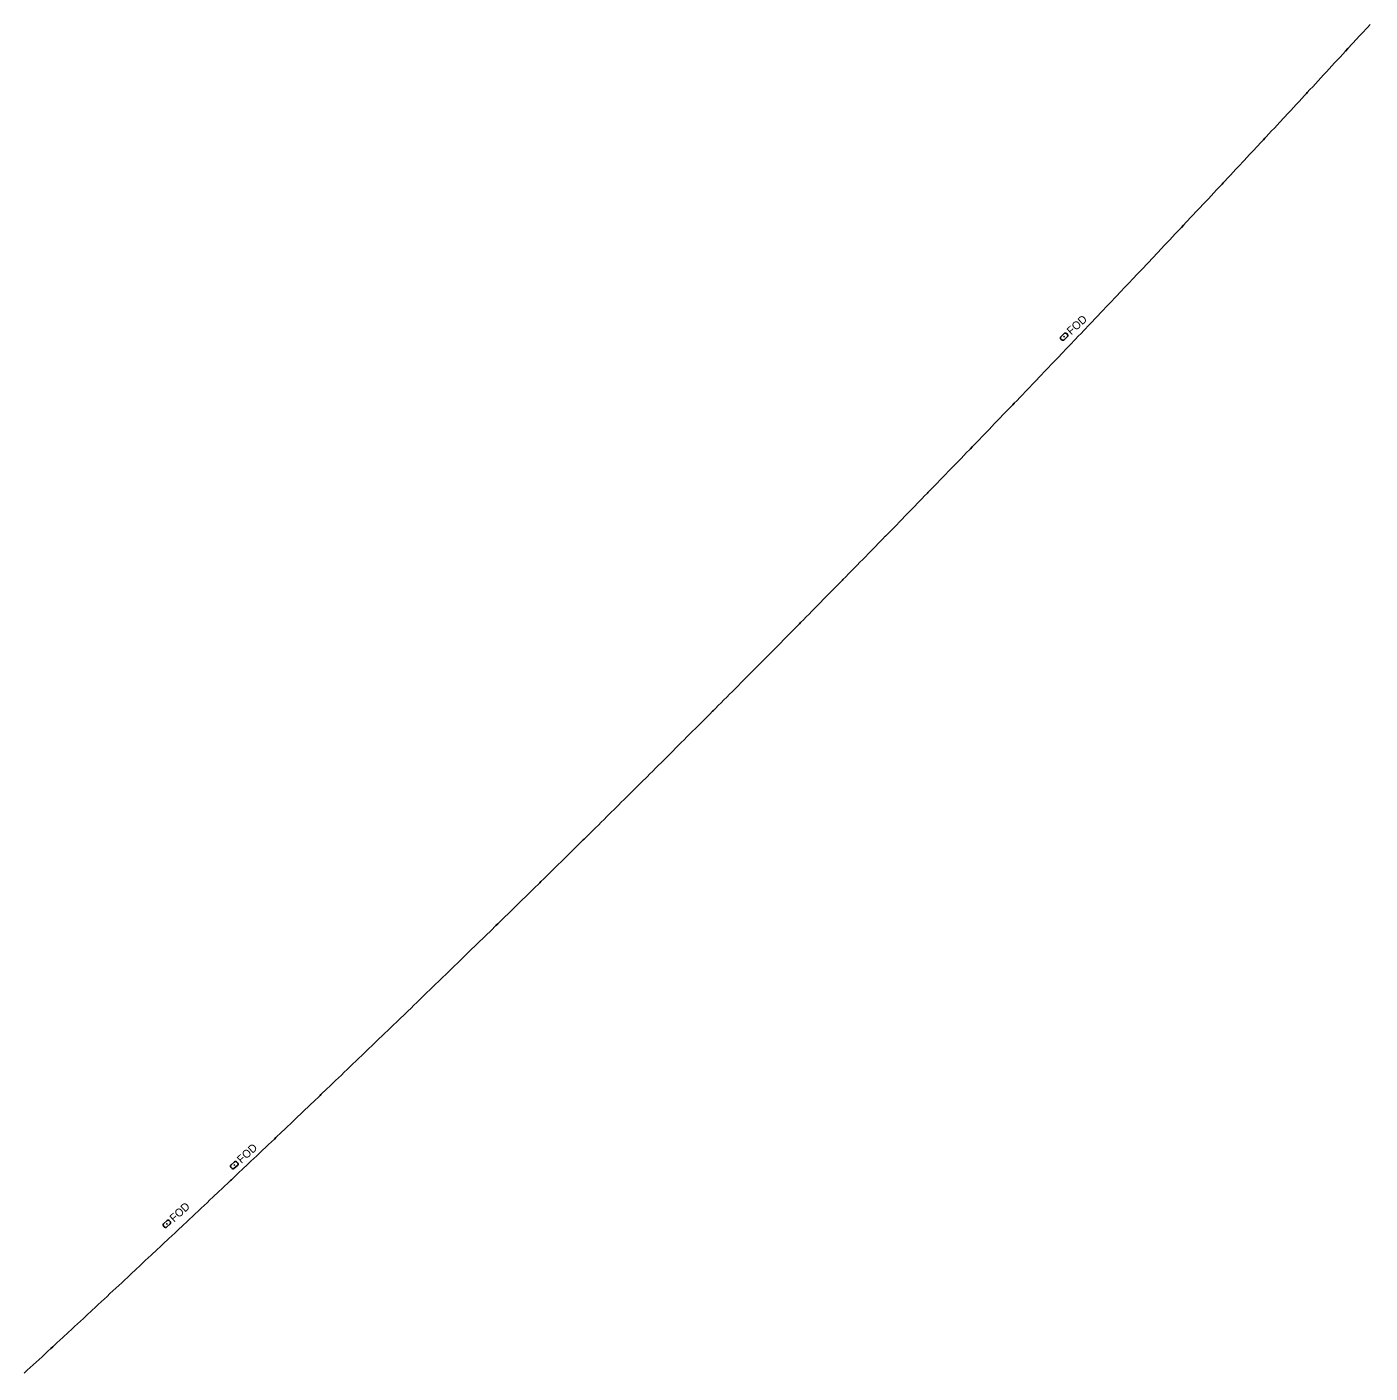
# Model space of a CAD drawing. Extents: x 1738869 to 1765295, y 463516 to 481552.
# Drawn here: x 1757969.7 to 1758301.3, y 478999.7 to 479332 of the extents above; entities that cross this region are included whole.
import ezdxf

# ---------------------------------------------------------------- set-up
doc = ezdxf.new("R2010")
doc.units = 0
doc.layers.add('D_ITS_Fiber', color=7, linetype='Continuous')
doc.layers.add('ITS Sign FO Delineator', color=7, linetype='Continuous')

msp = doc.modelspace()

# ---------------------------------------------------------------- linework, layer by layer
at = {"layer": 'D_ITS_Fiber'}
for points in [[(1758094.49, 479118.95), (1758095.19, 479119.64), (1758095.91, 479120.34), (1758096.3, 479120.72), (1758096.61, 479121.03), (1758097.32, 479121.73), (1758099.46, 479123.82), (1758100.16, 479124.52), (1758100.87, 479125.22), (1758101.59, 479125.92), (1758103.71, 479128.01), (1758104.42, 479128.71), (1758105.13, 479129.4), (1758106.54, 479130.8), (1758107.06, 479131.31), (1758107.25, 479131.5), (1758110.08, 479134.29), (1758110.79, 479134.99), (1758111.5, 479135.69), (1758112.2, 479136.39), (1758112.91, 479137.09), (1758115.74, 479139.89), (1758116.45, 479140.59), (1758117.15, 479141.29), (1758117.78, 479141.91), (1758117.85, 479141.98), (1758118.57, 479142.69), (1758119.27, 479143.39), (1758119.98, 479144.09), (1758120.68, 479144.79), (1758121.39, 479145.5), (1758122.8, 479146.9), (1758123.51, 479147.6), (1758124.21, 479148.3), (1758124.92, 479149), (1758127.03, 479151.11), (1758127.74, 479151.81), (1758128.44, 479152.51), (1758128.49, 479152.56), (1758129.14, 479153.21), (1758129.85, 479153.92), (1758131.26, 479155.33), (1758131.96, 479156.03), (1758132.66, 479156.73), (1758134.07, 479158.14), (1758134.78, 479158.84), (1758135.48, 479159.54), (1758136.18, 479160.25), (1758138.29, 479162.36), (1758139, 479163.07), (1758139.18, 479163.25), (1758139.69, 479163.76), (1758140.4, 479164.47), (1758141.1, 479165.18), (1758141.8, 479165.88), (1758142.51, 479166.59), (1758143.2, 479167.29), (1758143.91, 479167.99), (1758144.61, 479168.7), (1758146.71, 479170.81), (1758148.82, 479172.94), (1758149.52, 479173.64), (1758149.82, 479173.94), (1758150.22, 479174.34), (1758150.92, 479175.05), (1758151.62, 479175.76), (1758152.32, 479176.46), (1758153.02, 479177.17), (1758155.82, 479180), (1758156.52, 479180.71), (1758157.22, 479181.41), (1758157.92, 479182.12), (1758158.62, 479182.83), (1758160.02, 479184.24), (1758160.44, 479184.67), (1758160.71, 479184.95), (1758161.41, 479185.66), (1758162.11, 479186.37), (1758162.81, 479187.07), (1758163.51, 479187.78), (1758164.21, 479188.49), (1758167.69, 479192.03), (1758168.39, 479192.74), (1758170.49, 479194.88), (1758171.03, 479195.43), (1758171.18, 479195.58), (1758171.88, 479196.29), (1758172.57, 479197), (1758173.27, 479197.71), (1758173.97, 479198.42), (1758174.67, 479199.14), (1758175.36, 479199.84), (1758176.06, 479200.56), (1758178.14, 479202.69), (1758180.93, 479205.53), (1758181.64, 479206.26), (1758181.66, 479206.29), (1758183.7, 479208.38), (1758185.79, 479210.52), (1758186.48, 479211.23), (1758187.87, 479212.66), (1758188.56, 479213.37), (1758189.95, 479214.79), (1758190.65, 479215.51), (1758191.34, 479216.22), (1758192.04, 479216.95), (1758192.14, 479217.05), (1758192.73, 479217.65), (1758193.42, 479218.36), (1758194.11, 479219.07), (1758195.5, 479220.5), (1758196.19, 479221.22), (1758197.57, 479222.64), (1758200.34, 479225.5), (1758201.03, 479226.22), (1758201.72, 479226.94), (1758202.41, 479227.65), (1758202.63, 479227.87), (1758203.11, 479228.37), (1758207.25, 479232.66), (1758207.94, 479233.38), (1758208.63, 479234.09), (1758212.08, 479237.67), (1758212.77, 479238.39), (1758213.11, 479238.75), (1758213.46, 479239.11), (1758214.15, 479239.83), (1758214.84, 479240.55), (1758216.9, 479242.7), (1758218.28, 479244.14), (1758218.97, 479244.85), (1758219.66, 479245.57), (1758223.1, 479249.16), (1758223.56, 479249.65), (1758223.78, 479249.88), (1758224.47, 479250.6), (1758225.16, 479251.32), (1758226.53, 479252.76), (1758227.22, 479253.48), (1758228.59, 479254.92), (1758229.28, 479255.64), (1758229.96, 479256.36), (1758230.65, 479257.08), (1758232.02, 479258.52), (1758232.71, 479259.24), (1758233.39, 479259.96), (1758233.97, 479260.56), (1758234.07, 479260.67), (1758234.77, 479261.4), (1758236.82, 479263.57), (1758238.87, 479265.73), (1758239.56, 479266.45), (1758240.93, 479267.9), (1758241.61, 479268.62), (1758242.98, 479270.06), (1758243.67, 479270.79), (1758244.23, 479271.38), (1758244.25, 479271.4), (1758245.03, 479272.23), (1758247.76, 479275.12), (1758249.81, 479277.3), (1758250.49, 479278.02), (1758251.17, 479278.74), (1758251.86, 479279.47), (1758253.22, 479280.91), (1758254.59, 479282.37), (1758254.73, 479282.51), (1758255.27, 479283.09), (1758255.95, 479283.81), (1758258.67, 479286.71), (1758259.36, 479287.44), (1758260.04, 479288.16), (1758260.71, 479288.88), (1758261.4, 479289.61), (1758262.08, 479290.34), (1758262.76, 479291.07), (1758263.44, 479291.79), (1758264.12, 479292.51), (1758264.8, 479293.24), (1758265.05, 479293.51), (1758265.47, 479293.97), (1758266.16, 479294.7), (1758266.84, 479295.42), (1758267.52, 479296.15), (1758268.19, 479296.87), (1758268.87, 479297.6), (1758270.23, 479299.06), (1758270.91, 479299.78), (1758271.59, 479300.51), (1758272.27, 479301.24), (1758273.62, 479302.69), (1758274.3, 479303.42), (1758274.98, 479304.15), (1758275.36, 479304.55), (1758275.66, 479304.88), (1758276.33, 479305.6), (1758277.01, 479306.33), (1758277.69, 479307.06), (1758278.37, 479307.79), (1758279.05, 479308.52), (1758281.07, 479310.71), (1758281.75, 479311.43), (1758282.43, 479312.16), (1758283.1, 479312.89), (1758283.78, 479313.62), (1758284.46, 479314.35), (1758285.13, 479315.08), (1758285.62, 479315.61), (1758285.81, 479315.81), (1758286.48, 479316.54), (1758287.16, 479317.27), (1758287.83, 479318), (1758288.51, 479318.73), (1758289.18, 479319.46), (1758289.86, 479320.2), (1758290.54, 479320.92), (1758291.21, 479321.65), (1758291.89, 479322.39), (1758292.56, 479323.12), (1758293.23, 479323.85), (1758293.91, 479324.58), (1758294.58, 479325.31), (1758295.26, 479326.04), (1758295.85, 479326.69), (1758295.92, 479326.76), (1758297.95, 479328.97), (1758298.62, 479329.7), (1758299.3, 479330.44), (1758300.65, 479331.9), (1758301.32, 479332.64)], [(1757969.06, 478999.68), (1757969.79, 479000.36), (1757973.44, 479003.73), (1757974.17, 479004.41), (1757974.9, 479005.08), (1757975.64, 479005.76), (1757976.08, 479006.17), (1757976.36, 479006.43), (1757977.1, 479007.11), (1757977.82, 479007.78), (1757978.55, 479008.46), (1757980.01, 479009.81), (1757980.74, 479010.48), (1757981.47, 479011.17), (1757982.2, 479011.84), (1757983.66, 479013.19), (1757984.39, 479013.87), (1757985.85, 479015.23), (1757986.57, 479015.9), (1757987.14, 479016.43), (1757987.3, 479016.58), (1757988.03, 479017.26), (1757988.76, 479017.94), (1757989.48, 479018.61), (1757990.21, 479019.29), (1757991.67, 479020.65), (1757992.39, 479021.32), (1757993.12, 479022), (1757993.85, 479022.68), (1757994.58, 479023.36), (1757995.31, 479024.04), (1757996.76, 479025.4), (1757997.48, 479026.08), (1757998.25, 479026.8), (1757998.28, 479026.82), (1757998.94, 479027.44), (1757999.67, 479028.12), (1758000.39, 479028.8), (1758001.84, 479030.15), (1758002.57, 479030.84), (1758003.3, 479031.52), (1758004.75, 479032.88), (1758005.47, 479033.56), (1758006.2, 479034.24), (1758006.92, 479034.92), (1758008.37, 479036.28), (1758009.1, 479036.96), (1758009.2, 479037.06), (1758009.82, 479037.65), (1758010.55, 479038.33), (1758011.27, 479039.01), (1758012, 479039.69), (1758012.72, 479040.37), (1758013.44, 479041.05), (1758014.17, 479041.74), (1758014.89, 479042.42), (1758015.62, 479043.1), (1758017.06, 479044.47), (1758017.79, 479045.15), (1758018.51, 479045.83), (1758019.23, 479046.52), (1758019.95, 479047.2), (1758020.18, 479047.41), (1758020.68, 479047.88), (1758021.4, 479048.57), (1758022.12, 479049.25), (1758022.84, 479049.93), (1758024.29, 479051.3), (1758025.01, 479051.98), (1758025.73, 479052.67), (1758026.46, 479053.35), (1758027.18, 479054.04), (1758029.34, 479056.09), (1758030.79, 479057.47), (1758031.14, 479057.8), (1758031.5, 479058.15), (1758032.23, 479058.83), (1758033.67, 479060.2), (1758035.11, 479061.58), (1758035.83, 479062.26), (1758037.99, 479064.32), (1758040.87, 479067.07), (1758041.59, 479067.75), (1758042.08, 479068.22), (1758042.31, 479068.45), (1758043.75, 479069.82), (1758044.47, 479070.51), (1758045.18, 479071.19), (1758045.9, 479071.88), (1758046.62, 479072.57), (1758047.34, 479073.26), (1758048.06, 479073.95), (1758048.77, 479074.63), (1758050.21, 479076.01), (1758050.93, 479076.7), (1758051.64, 479077.39), (1758052.36, 479078.08), (1758052.98, 479078.67), (1758053.09, 479078.78), (1758053.8, 479079.45), (1758055.23, 479080.84), (1758055.95, 479081.53), (1758058.1, 479083.59), (1758058.81, 479084.28), (1758059.53, 479084.97), (1758060.25, 479085.66), (1758060.97, 479086.35), (1758063.77, 479089.06), (1758063.78, 479089.07), (1758064.54, 479089.81), (1758065.26, 479090.5), (1758065.98, 479091.19), (1758066.69, 479091.88), (1758067.41, 479092.57), (1758070.26, 479095.34), (1758071.69, 479096.72), (1758072.41, 479097.42), (1758073.12, 479098.11), (1758074.53, 479099.48), (1758074.67, 479099.62), (1758075.26, 479100.19), (1758075.98, 479100.88), (1758078.83, 479103.65), (1758080.97, 479105.73), (1758084.53, 479109.21), (1758085.24, 479109.91), (1758085.51, 479110.16), (1758085.95, 479110.59), (1758094.49, 479118.95), (1758094.49, 479118.95), (1758094.49, 479118.95), (1758094.49, 479118.95), (1758094.49, 479118.95), (1758094.49, 479118.95)]]:
    msp.add_lwpolyline(points, dxfattribs=at)
at = {"layer": 'ITS Sign FO Delineator'}
for p, q in [((1758224.94, 479255.54), (1758225.86, 479256.39)), ((1758226.62, 479255.56), (1758225.7, 479254.71)), ((1758020.07, 479051.01), (1758020.99, 479051.85)), ((1758021.75, 479051.02), (1758020.83, 479050.18)), ((1758003.43, 479036.51), (1758004.35, 479037.35)), ((1758005.11, 479036.52), (1758004.19, 479035.68))]:
    msp.add_line(p, q, dxfattribs=at)
for centre in [(1758225.78, 479255.55), (1758020.91, 479051.02), (1758004.27, 479036.51)]:
    msp.add_circle(centre, 0.05, dxfattribs=at)
for centre, major_axis in [((1758226.24, 479255.97), (-0.38, 0.414)), ((1758225.32, 479255.13), (0.38, -0.414)), ((1758020.45, 479050.59), (0.38, -0.414)), ((1758021.37, 479051.44), (-0.38, 0.414)), ((1758004.73, 479036.94), (-0.38, 0.414)), ((1758003.81, 479036.09), (0.38, -0.414))]:
    msp.add_ellipse(centre, major_axis=major_axis, ratio=0.666667, start_param=3.141593, end_param=6.283185, dxfattribs=at)

# ---------------------------------------------------------------- texts
for p in [(1758227.54, 479255.86), (1758022.67, 479051.33), (1758006.03, 479036.82)]:
    msp.add_text('FOD', height=1.968, rotation=42.5495, dxfattribs=at).set_placement(p)

doc.saveas('drawing.dxf')
